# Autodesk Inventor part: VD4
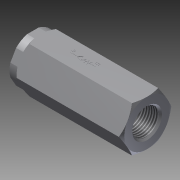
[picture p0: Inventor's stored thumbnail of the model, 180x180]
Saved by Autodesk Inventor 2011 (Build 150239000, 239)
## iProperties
Created: 2012-01
Part Number: VD4
Document SubType Name: Modeling
Designer: khramov
Density: 1 g/cm^3
Author: khramov
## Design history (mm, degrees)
derived "VD4_W1_30.ipt"
feature "Твердое тело1::VD4_W1_30.ipt" dims "d0" = 10
tag "Элемент создания маркировки1"
node "Твердое тело1"
